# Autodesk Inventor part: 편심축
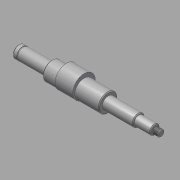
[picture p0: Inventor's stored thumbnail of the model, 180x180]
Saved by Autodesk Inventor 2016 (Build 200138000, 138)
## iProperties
Created: 2015-09
Part Number: 편심축
Material: 강철, 연강
Document SubType Name: Modeling
Designer: mduedu
Density: 1 g/cm^3
Appearance: 강철
Author: mduedu
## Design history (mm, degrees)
sketch "스케치1"
  geometry: L1 (-88.5, 0)-(88.5, 0); L2 (-88.5, 0)-(-88.5, 7.5); L3 (-88.5, 7.5)-(-47.35, 7.5); L4 (-47.35, 7.5)-(-47.35, 11.5); L5 (-47.35, 11.5)-(22.65, 11.5); L6 (22.65, 11.5)-(22.65, 7.5); L7 (22.65, 7.5)-(60.65, 7.5); L8 (60.65, 7.5)-(60.65, 6); L9 (60.65, 6)-(80.65, 6); L10 (80.65, 6)-(80.65, 3); L11 (80.65, 3)-(81.65, 3); L12 (81.65, 3)-(81.65, 4); L13 (81.65, 4)-(88.5, 4); L14 (88.5, 4)-(88.5, 0); 2 further points
  constraints: 28 end point, 10 parallel, 2 perpendicular, 1 coincident, 1 collinear, 1 horizontal, 1 midpoint
  dimensions: "d0" = 41.15 distance of L2.end L3.end; "d2" = 70 distance of L4.end L5.end; "d3" = 38 distance of L6.end L7.end; "d4" = 177 distance of L1.start L1.end; "d5" = 20 distance of L8.end L9.end; "d6" = 1 distance of L10.end L11.end; "d7" = 8 diameter of L13 L1; "d8" = 6 diameter of L11 L1; "d9" = 12 diameter of L9 L1; "d10" = 15 diameter of L7 L1; "d11" = 23 diameter of L5 L1; "d12" = 15 diameter of L3 L1
revolve "회전1" sketch "스케치1" stored, may be unused: angle "d13" = 90 deg
sketch "스케치2"
  geometry: L1 (-88.5, 7.5)-(-47.35, 7.5) reference; L2 (-88.5, -7.5)-(-88.5, 7.5) reference; L3 (88.5, -4)-(88.5, 4) reference; L4 (-88.5, 0)-(88.5, 0); L5 (-83.5, 7.5)-(-82.35, 7.5); L6 (-82.35, 7.5)-(-82.35, 7.15); L7 (-82.35, 7.15)-(-83.5, 7.15); L8 (-83.5, 7.15)-(-83.5, 7.5); 1 further point
  constraints: 10 end point, 2 midpoint, 2 parallel, 1 horizontal, 1 perpendicular, 1 point on line
  dimensions: "d14" = 5 distance between parallel lines of L8 L2; "d15" = 14.3 diameter of L7 L4; "d16" = 1.15 distance of L6.end L7.end
revolve "회전2" sketch "스케치2" stored, may be unused: angle "d17" = 90 deg
node "작업 평면1"
sketch "스케치3"
  geometry: C1 r 11.5 at (0, 0) reference; C2 r 14 at (0, 2.5); 1 further point
  constraints: 1 centre point, 1 tangent, 1 vertical alignment
  dimensions: "d19" = 28 diameter of C2
extrude "돌출1" join sketch "스케치3" distance "d21" = 22; taper "d22" = 0 deg
node "작업 평면2"
sketch "스케치4"
  geometry: L1 (10, 7.5)-(10, -7.5) reference; L2 (-10, 6)-(-10, -6) reference; L3 (10, 0)-(-10, 0); L4 (-5, -2)-(3, -2); L5 (3, 2)-(-5, 2); A1 r 2 centre (3, 0) between (3, -2) and (3, 2); A2 r 2 centre (-5, 0) between (-5, 2) and (-5, -2); 1 further point
  constraints: 6 end point, 4 point on circle, 4 tangent, 2 centre point, 2 midpoint, 2 parallel, 1 point on line
  dimensions: "d23" = 4 distance between parallel lines of L5 L4; "d25" = 12 dimension on A2 A1; "d26" = 3 distance edge to line of A2 L2
extrude "돌출2" cut sketch "스케치4" distance "d27" = 2.5; taper "d28" = 0 deg
chamfer "모따기1" distance "d29" = 1; stored, may be unused: second distance "d30" = 2, angle "d31" = 45 deg
feature "스레드1" dims "d32" = 10, "d33" = 0
chamfer "모따기2" distance "d34" = 1; stored, may be unused: second distance "d35" = 2, angle "d36" = 45 deg
chamfer "모따기3" distance "d37" = 1; stored, may be unused: second distance "d38" = 2, angle "d39" = 45 deg
node "솔리드1"
